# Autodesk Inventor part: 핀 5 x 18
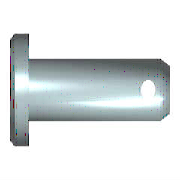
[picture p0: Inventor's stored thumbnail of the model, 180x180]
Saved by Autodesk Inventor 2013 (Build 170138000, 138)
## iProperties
Created: 2012-02
Part Number: 핀 5 x 18
Material: 강철
Description: 머리가 있는 클레비스 핀
Document SubType Name: Modeling
Standard: ISO 2341
Designer: test
Standard Revision: Second edition 1986-11-01
Standards Organization: ISO
Language: ko-KR
Size Designation: B - 5 x 18
Categories: <MemberInstance><Categories><Category DisplayName="조임쇠" InternalName="e4da775c-781d-43d5-af7c-5136215cf5a6" Mnemonic="FSTN"><Category DisplayName="핀" InternalNa
Density: 7.85 g/cm^3
IsCustomPart: 1
Author: test
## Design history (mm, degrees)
sketch "스케치1"
  geometry: L1 (-1.6, 0)-(-1.6, 4); L2 (-1.6, 4)-(0, 4); L3 (0, 4)-(0, 2.5); L4 (0, 2.5)-(18, 2.5); L5 (18, 2.5)-(18, 0); L6 (-1.6, 0)-(18, 0); L7 (-4, 0)-(17, 0) reference; L8 (0, -0.98)-(0, 3.08) reference; C1 r 0.6 at (15.1, 0)
  constraints: 12 end point, 3 parallel, 2 collinear, 2 perpendicular, 1 centre point, 1 point on line, 1 vertical
  dimensions: "d0" = 5 diameter of L4 L6 (= NND); "d1" = 8 diameter of L2 L6 (= KOD); "d2" = 1.6 distance of L1.end L2.end (= KOH); "d3" = 18 distance of L3.end L4.end (= NLG); "d5" = 2.9 distance from line of L5 C1.centre (= DIST); "d6" = 1.2 diameter of C1 (= BOR)
revolve "본체" stored, may be unused: angle "d4" = 90 deg
extrude "구멍" cut sketch "스케치1" stored distance "d7" = 5 (= NND); taper "d8" = 0 deg
workaxis "Work Axis1"
workplane "Work Plane1"
sketch "스케치2"
  geometry: L1 (-18, 1.345)-(-16, 2.5) reference; L2 (-16, 2.5)-(-15.7, 2.5) reference; L3 (-15.7, 2.5)-(-15.7, -2.5) reference; L4 (-15.7, -2.5)-(-16, -2.5) reference; L5 (-16, -2.5)-(-18, -1.345) reference; L6 (-18, -1.345)-(-18, 1.345) reference; L7 (0.6, 4)-(1.6, 3) reference; L8 (1.6, 3)-(1.6, -3) reference; L9 (1.6, -3)-(0.6, -4) reference; L10 (0.6, -4)-(0, -4) reference; L11 (0, -4)-(0, -2.5) reference; L12 (0, -2.5)-(-14.5, -2.5) reference; L13 (-14.5, -2.5)-(-14.5, 2.5) reference; L14 (-14.5, 2.5)-(0, 2.5) reference; L15 (0, 2.5)-(0, 4) reference; L16 (0, 4)-(0.6, 4) reference; 1 further point
  node "절단 모서리 투영1"
sketch "스케치3"
  geometry: L1 (-1.6, 3)-(-0.6, 4) reference; L2 (-0.6, 4)-(0, 4) reference; L3 (0, 4)-(0, 2.5) reference; L4 (0, 2.5)-(16, 2.5) reference; L5 (16, 2.5)-(18, 1.345) reference; L6 (18, 1.345)-(18, -1.345) reference; L7 (18, -1.345)-(16, -2.5) reference; L8 (16, -2.5)-(0, -2.5) reference; L9 (0, -2.5)-(0, -4) reference; L10 (0, -4)-(-0.6, -4) reference; L11 (-0.6, -4)-(-1.6, -3) reference; L12 (-1.6, -3)-(-1.6, 3) reference; C1 r 0.6 at (15.1, 0) reference; 1 further point
  node "절단 모서리 투영2"
node "작업 평면4"
body "Solid1"
chamfer "모따기1" distance "d9" = 1 (= PHH2); stored, may be unused: angle "d10" = 45 deg (= FAWI2), second distance "d16" = 1 (= PHH2)
chamfer "모따기2" distance "d11" = 2 (= PHH1); stored, may be unused: angle "d12" = 30 deg (= FAWI1), second distance "d17" = 2 (= PHH1)
other parameters: "PHH1" = 2 [user parameter; used in 2 equation terms], "PHH2" = 1 [user parameter; used in 2 equation terms], "KOD" = 8 [user parameter; used in 1 equation term], "KOH" = 1.6 [user parameter; used in 1 equation term], "NND" = 5 [user parameter; used in 2 equation terms], "FAWI1" = 30 deg [user parameter; used in 1 equation term], "FAWI2" = 45 deg [user parameter; used in 1 equation term], "DIST" = 2.9 [user parameter; used in 1 equation term], "BOR" = 1.2 [user parameter; used in 1 equation term], "NLG" = 18 [user parameter; used in 1 equation term], "d13" = 0, "d14" = 0, "d27" = 0, "d28" = 0, "d29" = 0, "d30" = 0, "d31" = 0, "d32" = 15.1
